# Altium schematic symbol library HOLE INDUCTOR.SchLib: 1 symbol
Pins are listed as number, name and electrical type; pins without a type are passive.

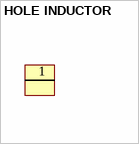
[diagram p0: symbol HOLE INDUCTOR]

## HOLE INDUCTOR
designator H?, comment NONE
HOLE INDUCTOR; Manufacturer: Used in BOM report; SymbolVersion: 2014 - 10 - 22; SymbolCreator: A0412036; CompType: Used in some BOM reports.  Useful for finding later.; U/M: EA
footprint HOLE M3 (M3 X0.5 HOLE NO METAL)
footprint HOLE INDUCTOR (M3 X0.5 HOLE NO METAL)
pins: 1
